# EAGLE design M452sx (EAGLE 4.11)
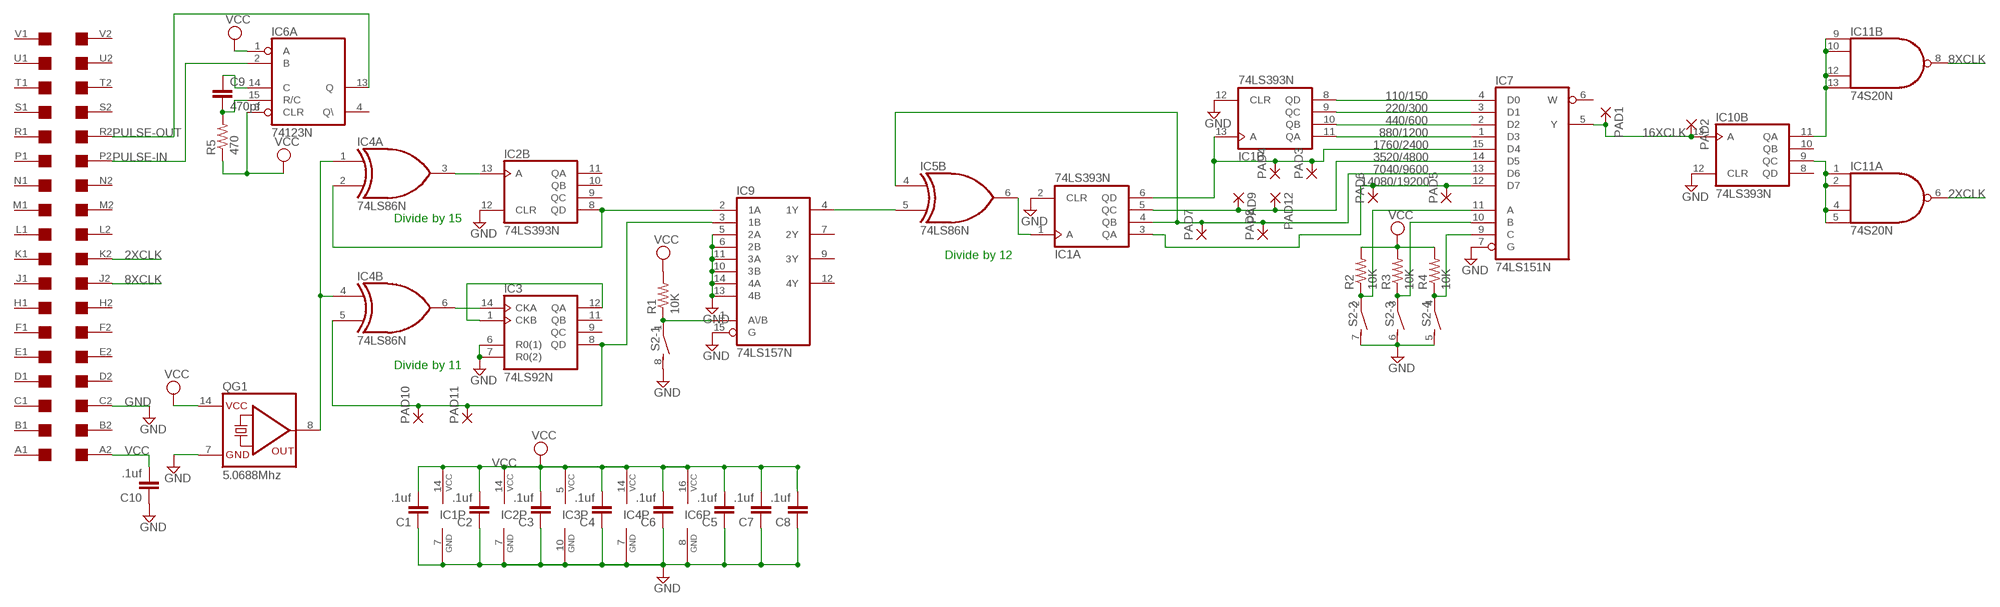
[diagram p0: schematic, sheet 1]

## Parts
C1  .1uf  C-EU050-025X075  [C050-025X075]
C2  .1uf  C-EU050-025X075  [C050-025X075]
C3  .1uf  C-EU050-025X075  [C050-025X075]
C4  .1uf  C-EU050-025X075  [C050-025X075]
C5  .1uf  C-EU050-025X075  [C050-025X075]
C6  .1uf  C-EU050-025X075  [C050-025X075]
C7  .1uf  C-EU050-025X075  [C050-025X075]
C8  .1uf  C-EU050-025X075  [C050-025X075]
C9  470pf  C-EU050-025X075  [C050-025X075]
C10  .1uf  C-EU050-025X075  [C050-025X075]
IC1  74LS393N  [DIL14]
IC2  74LS393N  [DIL14]
IC3  74LS92N  [DIL14]
IC4  74LS86N  [DIL14]
IC5  74LS86N  [DIL14]
IC6  74123N  [DIL16]
IC7  74LS151N  74151N  [DIL16]
IC9  74LS157N  [DIL16]
IC10  74LS393N  [DIL14]
IC11  74S20N  [DIL14]
PAD1  1,6/0,8  [1,6/0,8]
PAD2  1,6/0,8  [1,6/0,8]
PAD3  1,6/0,8  [1,6/0,8]
PAD4  1,6/0,8  [1,6/0,8]
PAD5  1,6/0,8  [1,6/0,8]
PAD6  1,6/0,8  [1,6/0,8]
PAD7  1,6/0,8  [1,6/0,8]
PAD8  1,6/0,8  [1,6/0,8]
PAD9  1,6/0,8  [1,6/0,8]
PAD10  1,6/0,8  [1,6/0,8]
PAD11  1,6/0,8  [1,6/0,8]
PAD12  1,6/0,8  [1,6/0,8]
QG1  5.0688Mhz  QG5860  [DIL14S]
R1  10K  R-US_0204/7  [0204/7]
R2  10K  R-US_0204/7  [0204/7]
R3  10K  R-US_0204/7  [0204/7]
R4  10K  R-US_0204/7  [0204/7]
R5  470  R-US_0204/7  [0204/7]
S2  DIP04S  [DIP04S]
U$1  DEC-FLIPCHIP  [DEC-FLIPCHIP]

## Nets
2XCLK: IC11.6(A:O) U$1.K2
8XCLK: IC11.8(B:O) U$1.J2
16XCLK: IC7.5(Y) IC10.13(B:A) PAD1.1(P) PAD2.1(P)
110/150: IC1.8(B:QD) IC7.4(D0)
220/300: IC1.9(B:QC) IC7.3(D1)
440/600: IC1.10(B:QB) IC7.2(D2)
880/1200: IC1.11(B:QA) IC7.1(D3)
1760/2400: IC1.6(A:QD) IC1.13(B:A) IC7.15(D4) PAD3.1(P) PAD4.1(P)
3520/4800: IC1.5(A:QC) IC7.14(D5) PAD9.1(P) PAD12.1(P)
7040/9600: IC1.4(A:QB) IC5.4(B:I0) IC7.13(D6) PAD7.1(P) PAD8.1(P)
14080/19200: IC1.3(A:QA) IC7.12(D7) PAD5.1(P) PAD6.1(P)
GND: C1.1 C2.1 C3.1 C4.1 C5.1 C6.1 C7.1 C8.1 C10.1 IC1.2(A:CLR) IC1.7(P:GND) IC1.12(B:CLR) IC2.7(P:GND) IC2.12(B:CLR) IC3.6(R0(1)) IC3.7(R0(2)) IC3.10(GND) IC4.7(P:GND) IC6.8(P:GND) IC7.7(G) IC9.5(2A) IC9.6(2B) IC9.10(3B) IC9.11(3A) IC9.13(4B) IC9.14(4A) IC9.15(G) IC10.12(B:CLR) QG1.7(GND) S2.5 S2.6 S2.7 S2.8 U$1.C2
N$1: IC4.1(A:I0) IC4.4(B:I0) QG1.8(OUT)
N$2: IC2.8(B:QD) IC4.2(A:I1) IC9.2(1A)
N$3: IC3.8(QD) IC4.5(B:I1) IC9.3(1B) PAD10.1(P) PAD11.1(P)
N$4: IC3.1(CKB) IC3.12(QA)
N$5: IC3.14(CKA) IC4.6(B:O)
N$6: IC2.13(B:A) IC4.3(A:O)
N$8: IC7.11(A) R2.1 S2.2
N$9: IC5.5(B:I1) IC9.4(1Y)
N$10: IC10.9(B:QC) IC11.1(A:I0) IC11.2(A:I1) IC11.4(A:I2) IC11.5(A:I3)
N$11: IC1.1(A:A) IC5.6(B:O)
N$12: IC10.11(B:QA) IC11.9(B:I0) IC11.10(B:I1) IC11.12(B:I2) IC11.13(B:I3)
N$13: IC7.10(B) R3.1 S2.3
N$14: IC7.9(C) R4.1 S2.4
N$17: IC9.1(A\/B) R1.1 S2.1
N$21: C9.2 IC6.15(A:R/C) R5.2
N$22: C9.1 IC6.14(A:C)
PULSE-IN: IC6.2(A:B) U$1.P2
PULSE-OUT: IC6.13(A:Q) U$1.R2
VCC: C1.2 C2.2 C3.2 C4.2 C5.2 C6.2 C7.2 C8.2 C10.2 IC1.14(P:VCC) IC2.14(P:VCC) IC3.5(VCC) IC4.14(P:VCC) IC6.1(A:A) IC6.3(A:CLR) IC6.16(P:VCC) QG1.14(VCC) R1.2 R2.2 R3.2 R4.2 R5.1 U$1.A2
Unconnected: IC2.1(A:A) IC2.2(A:CLR) IC2.3(A:QA) IC2.4(A:QB) IC2.5(A:QC) IC2.6(A:QD) IC2.9(B:QC) IC2.10(B:QB) IC2.11(B:QA) IC3.9(QC) IC3.11(QB) IC4.8(C:O) IC4.9(C:I0) IC4.10(C:I1) IC4.11(D:O) IC4.12(D:I0) IC4.13(D:I1) IC5.1(A:I0) IC5.2(A:I1) IC5.3(A:O) IC5.8(C:O) IC5.9(C:I0) IC5.10(C:I1) IC5.11(D:O) IC5.12(D:I0) IC5.13(D:I1) IC6.4(A:Q\) IC6.5(B:Q) IC6.6(B:C) IC6.7(B:R/C) IC6.9(B:A) IC6.10(B:B) IC6.11(B:CLR) IC6.12(B:Q\) IC7.6(W) IC9.7(2Y) IC9.9(3Y) IC9.12(4Y) IC10.1(A:A) IC10.2(A:CLR) IC10.3(A:QA) IC10.4(A:QB) IC10.5(A:QC) IC10.6(A:QD) IC10.8(B:QD) IC10.10(B:QB) U$1.A1 U$1.B1 U$1.B2 U$1.C1 U$1.D1 U$1.D2 U$1.E1 U$1.E2 U$1.F1 U$1.F2 U$1.H1 U$1.H2 U$1.J1 U$1.K1 U$1.L1 U$1.L2 U$1.M1 U$1.M2 U$1.N1 U$1.N2 U$1.P1 U$1.R1 U$1.S1 U$1.S2 U$1.T1 U$1.T2 U$1.U1 U$1.U2 U$1.V1 U$1.V2

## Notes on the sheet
- Divide by 15
- Divide by 12
- Divide by 11

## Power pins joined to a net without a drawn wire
GND: IC5.7(P:GND) IC7.8(GND) IC9.8(GND) IC10.7(P:GND) IC11.7(P:GND)
VCC: IC5.14(P:VCC) IC7.16(VCC) IC9.16(VCC) IC10.14(P:VCC) IC11.14(P:VCC)

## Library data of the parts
C1-C10 = rcl:C-EU: CAPACITOR, European symbol
IC1 IC2 IC10 = 74xx-us:74*393: Dual 4-bit decade and binary COUNTER
IC3 = 74xx-us:74*92: Decade, divide by twelve and binary COUNTER
IC4 IC5 = 74xx-us:74*86: Quad 2-input EXCLUSIV-OR (XOR) gate
IC6 = 74xx-us:74*123: Retriggerable monostable MULTIVIBRATOR
IC7 = 74xx-us:74*151: Data SELECTOR/MULTIPLEXER
IC9 = 74xx-us:74*157: Quadruple 2-line to 1-line data SELECTOR/MULTIPLEXER
IC11 = 74xx-us:74*20: Dual 4-input NAND gate
PAD1-PAD12 = wirepad:1,6/0,8: THROUGH-HOLE PAD
QG1 = crystal:QG5860: CRYSTAL RESONATOR
R1-R5 = rcl:R-US_: RESISTOR, American symbol
S2 = switch-dil:DIP04S: DIL/CODE SWITCH
U$1 = con-dec:DEC-FLIPCHIP: DEC Flip-Chip single card fingers

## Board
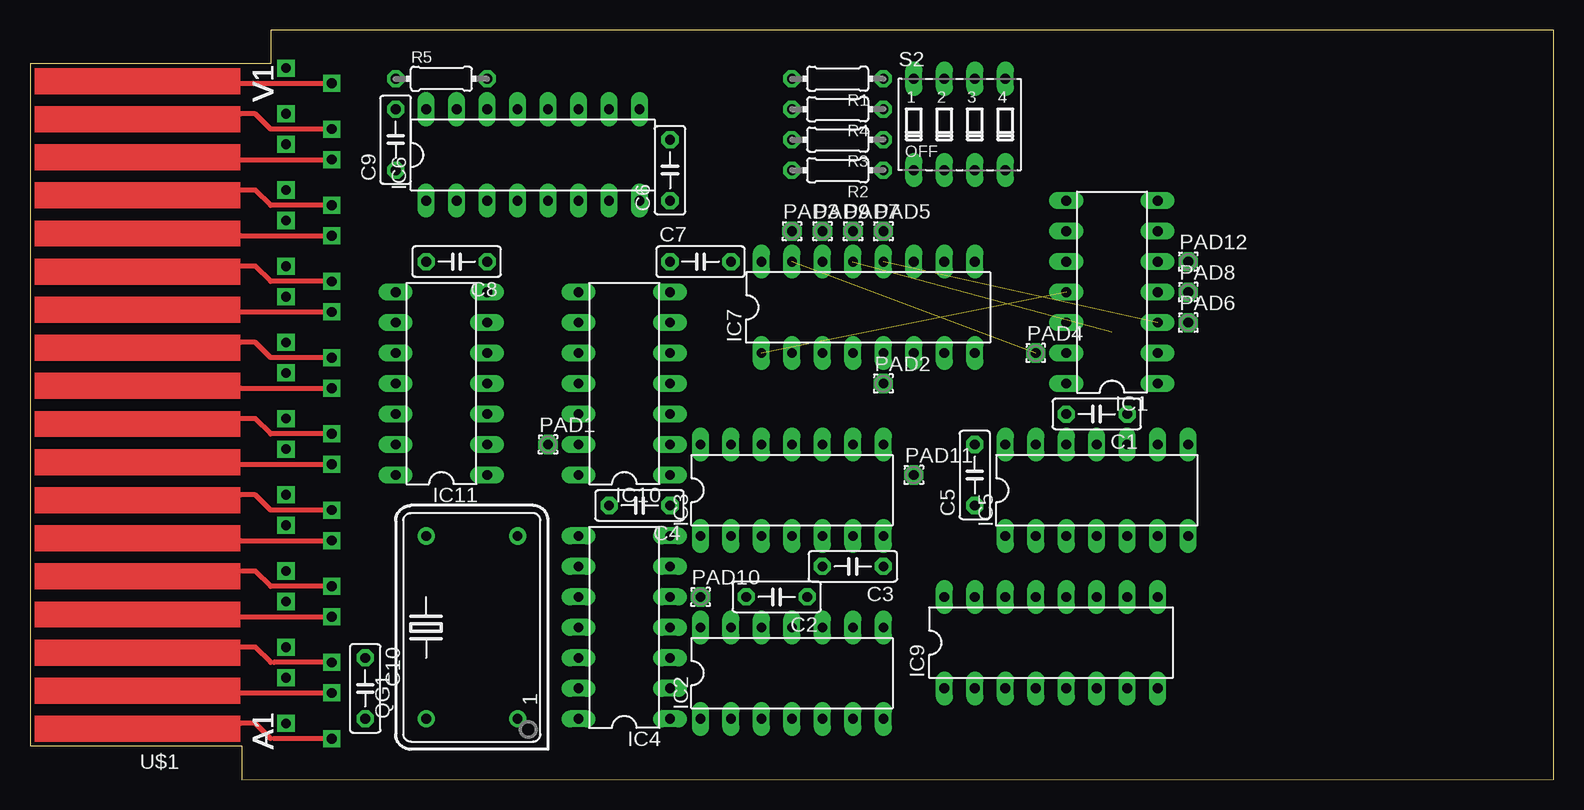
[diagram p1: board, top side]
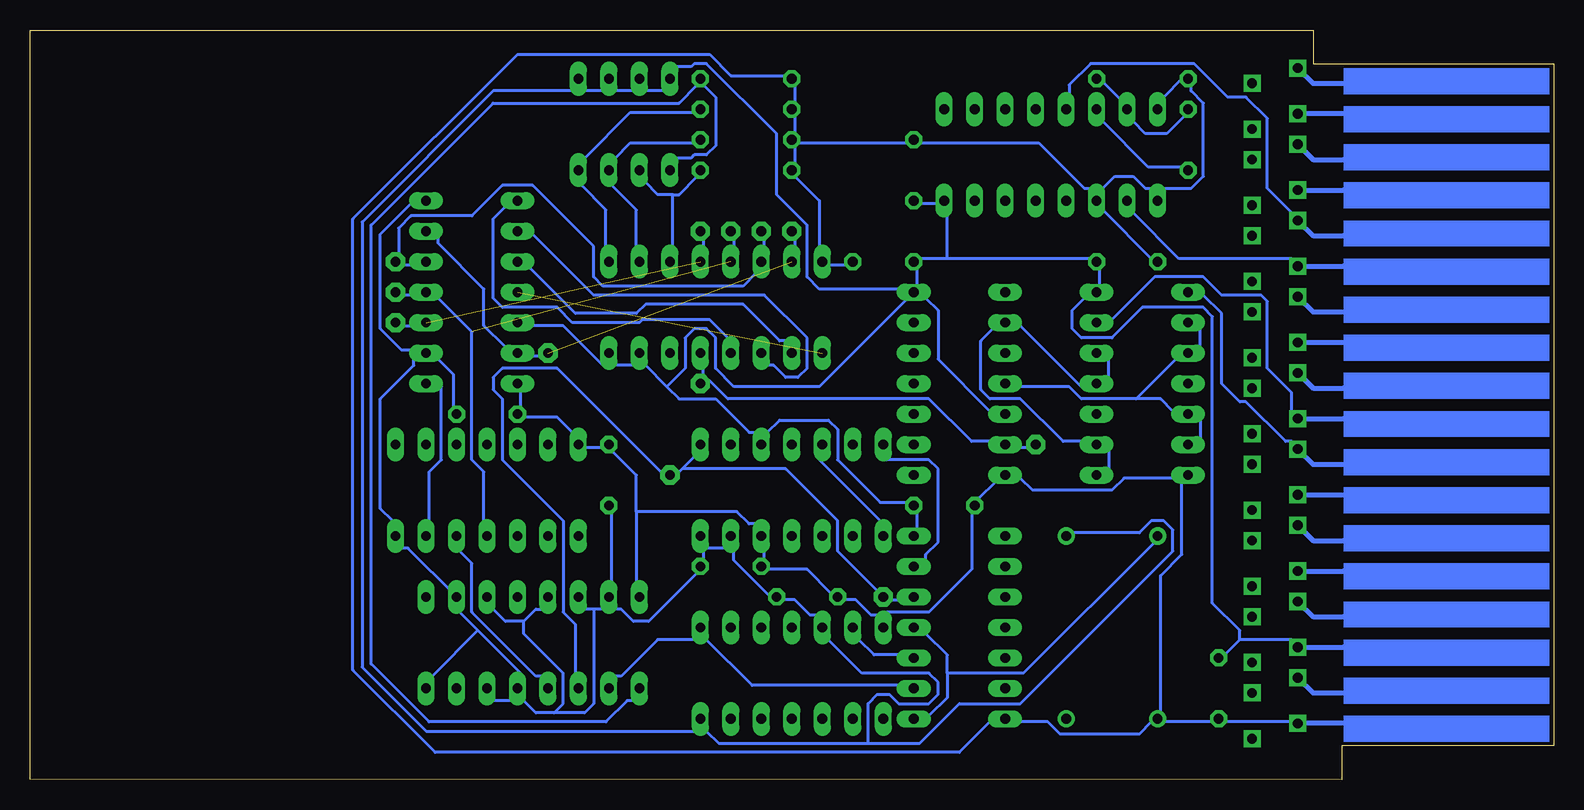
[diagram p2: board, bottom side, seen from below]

Size 126.98 x 62.48 mm. Coordinates in mm from the lower left corner, seen from the top.
Outline: 0,2.83 17.65,2.83 17.65,0 126.98,0.04 126.98,62.45 20.06,62.48 20.06,59.65 0,59.65 0,2.83
Copper layers (1*16): Top 0.035mm / dielectric 1.5mm / Bottom 0.035mm
Design rules "10mils": minimum track width 10mil, minimum drill 28mil, track to track 15mil, track to pad 10mil, pad to pad 10mil, via to via 10mil, smd to smd 10mil, copper to edge 40mil, drill to drill 10mil, minimum pad ring 12mil, minimum via ring 8mil, stop-mask expansion 0mil, vias tented up to drill 0mil, thermal gap 10mil

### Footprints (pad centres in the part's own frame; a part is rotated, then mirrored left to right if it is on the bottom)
C050-025X075 = drill 0.813 octagon: 1 -2.54,0; 2 2.54,0
DIL14 = drill 0.813 long: 1 -7.62,-3.81; 2 -5.08,-3.81; 3 -2.54,-3.81; 4 0,-3.81; 5 2.54,-3.81; 6 5.08,-3.81; 7 7.62,-3.81; 8 7.62,3.81; 9 5.08,3.81; 10 2.54,3.81; 11 0,3.81; 12 -2.54,3.81; 13 -5.08,3.81; 14 -7.62,3.81
DIL16 = drill 0.813 long: 1 -8.89,-3.81; 2 -6.35,-3.81; 3 -3.81,-3.81; 4 -1.27,-3.81; 5 1.27,-3.81; 6 3.81,-3.81; 7 6.35,-3.81; 8 8.89,-3.81; 9 8.89,3.81; 10 6.35,3.81; 11 3.81,3.81; 12 1.27,3.81; 13 -1.27,3.81; 14 -3.81,3.81; 15 -6.35,3.81; 16 -8.89,3.81
1,6/0,8 = drill 0.813 pad 1.6 octagon: 1 0,0
DIL14S = drill 0.813 round: 1 -7.62,-3.81; 7 7.62,-3.81; 8 7.62,3.81; 14 -7.62,3.81
0204/7 = drill 0.813 octagon: 1 -3.81,0; 2 3.81,0
DIP04S = drill 0.813 long: 1 -3.81,-3.81; 2 -1.27,-3.81; 3 1.27,-3.81; 4 3.81,-3.81; 5 3.81,3.81; 6 1.27,3.81; 7 -1.27,3.81; 8 -3.81,3.81
DEC-FLIPCHIP = drill 0.813 square: A1 -7.62,27.94; A2 -3.81,26.67; B1 -7.62,24.13; B2 -3.81,22.86; C1 -7.62,21.59; C2 -3.81,20.32; D1 -7.62,17.78; D2 -3.81,16.51; E1 -7.62,15.24; E2 -3.81,13.97; F1 -7.62,11.43; F2 -3.81,10.16; H1 -7.62,8.89; H2 -3.81,7.62; J1 -7.62,5.08; J2 -3.81,3.81; K1 -7.62,2.54; K2 -3.81,1.27; L1 -7.62,-1.27; L2 -3.81,-2.54; M1 -7.62,-3.81; M2 -3.81,-5.08; N1 -7.62,-7.62; N2 -3.81,-8.89; P1 -7.62,-10.16; P2 -3.81,-11.43; R1 -7.62,-13.97; R2 -3.81,-15.24; S1 -7.62,-16.51; S2 -3.81,-17.78; T1 -7.62,-20.32; T2 -3.81,-21.59; U1 -7.62,-22.86; U2 -3.81,-24.13; V1 -7.62,-26.67; V2 -3.81,-27.94

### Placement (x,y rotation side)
C1  88.9,30.48 180 top
C2  62.22,15.24 180 top
C3  68.58,17.78 180 top
C4  50.79,22.86 180 top
C5  78.73,25.4 90 top
C6  53.34,50.8 90 top
C7  55.88,43.18 0 top
C8  35.55,43.18 180 top
C9  30.48,53.34 90 top
C10  27.94,7.62 270 top
IC1  90.17,40.64 90 top
IC2  63.49,8.89 0 top
IC3  63.49,24.13 0 top
IC4  49.52,12.7 90 top
IC5  88.9,24.13 0 top
IC6  41.9,52.07 0 top
IC7  69.84,39.37 0 top
IC9  85.09,11.43 0 top
IC10  49.52,33.02 90 top
IC11  34.28,33.02 90 top
PAD1  43.17,27.94 0 top
PAD2  71.12,33.02 0 top
PAD3  63.49,45.72 0 top
PAD4  83.81,35.56 0 top
PAD5  71.12,45.72 0 top
PAD6  96.52,38.1 0 top
PAD7  68.58,45.72 0 top
PAD8  96.52,40.64 0 top
PAD9  66.04,45.72 0 top
PAD10  55.88,15.24 0 top
PAD11  73.66,25.4 0 top
PAD12  96.52,43.18 0 top
QG1  36.82,12.7 90 top
R1  67.31,58.42 180 top
R2  67.31,50.8 180 top
R3  67.31,53.34 180 top
R4  67.31,55.88 180 top
R5  34.28,58.42 0 top
S2  77.47,54.61 0 top
U$1  17.52,31.37 180 top

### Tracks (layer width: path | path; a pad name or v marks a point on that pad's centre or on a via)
2XCLK
  Bottom 0.254: U$1.K2 21.84,30.73 21.84,32.26 23.87,34.29 23.87,39.88 24.38,40.39 27.68,40.39 29.21,41.91 33.27,41.91 36.82,38.35 IC11.6
8XCLK
  Bottom 0.254: U$1.J2 21.84,28.19 22.35,28.19 25.65,31.5 26.16,31.5 27.68,33.02 27.68,38.86 29.21,40.39 IC11.8
16XCLK
  Bottom 0.254: PAD1.1 43.94,27.69 44.45,27.69 IC10.13 46.98,28.19 48.51,28.19 52.06,31.75 68.83,31.75 70.35,33.27 PAD2.1 70.86,33.78 70.86,34.29 IC7.5
110/150
  Bottom 0.254: IC7.4 68.83,36.83 70.35,38.35 75.94,38.35 76.2,38.1 81.78,38.1 83.05,39.37 87.62,39.37 88.39,40.13 88.39,46.74 87.37,47.75 IC1.8
220/300
  Bottom 0.254: IC7.3 65.53,34.54 65.02,34.54 64,33.53 62.99,33.53 62.22,34.29 62.22,36.83 65.78,40.39 80.01,40.39 85.09,45.47 IC1.9
440/600
  Bottom 0.254: IC7.2 64,36.58 64.51,36.58 67.56,39.62 75.69,39.62 76.45,38.86 81.53,38.86 85.34,42.67 IC1.10
880/1200  (1 unrouted)
1760/2400  (1 unrouted)
  Bottom 0.254: PAD4.1 84.58,35.31 85.09,35.31 IC1.13 87.37,36.07 89.15,37.85 89.15,40.89 92.96,44.7 92.96,45.21 IC1.6 | IC7.15 63.24,44.45 63.24,44.96 PAD3.1
3520/4800
  Bottom 0.254: IC1.5 95.25,42.93 95.75,42.93 PAD12.1 96.26,43.94 96.26,45.97 95.25,46.99 90.17,46.99 87.62,49.53 85.09,49.53 80.01,44.45 80.01,41.91 79.24,41.15 67.56,41.15 66.54,42.16 IC7.14 65.78,44.45 65.78,44.96 PAD9.1
7040/9600  (1 unrouted)
  Bottom 0.254: IC5.4 89.15,21.59 89.15,25.65 90.17,26.67 90.17,37.34 92.96,40.13 IC1.4 95.25,40.39 95.75,40.39 PAD8.1 | IC7.13 68.32,44.45 68.32,44.96 PAD7.1
14080/19200  (1 unrouted)
  Bottom 0.254: IC7.12 70.86,44.45 70.86,44.96 PAD5.1 | IC1.3 95.25,37.85 95.75,37.85 PAD6.1
GND
  Bottom 0.254: 57.14,3.05 69.59,3.05 70.61,4.06 IC2.7 71.62,4.06 93.98,4.06 99.31,9.4 99.31,46.48 88.39,57.4 81.78,57.4 S2.5 80.77,57.4 79.24,57.4 S2.6 78.23,57.4 76.7,57.4 S2.7 75.69,57.4 74.16,57.4 S2.8 73.15,59.44 71.88,59.44 71.62,59.69 70.61,59.69 64.77,53.85 64.77,48.77 62.22,46.23 62.22,41.91 61.21,40.89 54.6,40.89 IC10.7 | 57.14,3.05 52.83,3.05 49.52,6.35 44.45,6.35 31.75,19.05 31.75,20.83 32.51,21.59 33.52,21.59 34.54,20.57 40.13,20.57 QG1.7 | 80.01,14.22 80.77,14.22 IC9.14 | 80.01,14.22 79.24,14.22 IC9.15 | C5.1 78.48,22.35 78.48,16.51 IC9.15 | IC9.15 78.23,14.22 77.72,14.22 76.7,13.21 75.43,13.21 71.37,17.27 C3.1 70.86,18.29 70.86,19.05 IC3.7 70.61,19.3 69.08,19.3 IC3.6 68.32,19.05 68.32,18.29 65.27,15.24 C2.1 64.26,14.99 63.24,14.99 61.97,13.72 61.46,13.72 IC2.12 60.45,11.68 57.65,8.89 52.06,8.89 51.3,8.13 51.3,7.11 52.06,6.35 54.6,6.35 55.37,7.11 56.38,7.11 57.14,6.35 57.14,3.05 | C1.1 91.69,30.99 91.69,33.78 92.96,35.05 IC1.2 | IC1.7 95.25,48.01 97.79,45.47 97.79,37.59 96.01,35.81 95.25,35.81 IC1.2 | 85.85,13.21 84.83,14.22 84.32,14.22 IC9.13 | 85.85,13.21 87.37,13.21 88.39,14.22 IC9.11 | IC9.5 86.86,6.6 88.39,6.6 IC9.6 | 89.66,12.45 86.1,8.89 IC9.5 | 89.66,12.45 91.18,13.97 IC9.10 95.5,19.3 96.01,19.3 IC5.7 96.77,21.59 97.79,22.61 97.79,31.75 94.99,34.54 94.99,35.05 IC1.2 | 89.66,12.45 93.47,8.64 IC9.8 | 85.85,13.21 85.85,12.19 82.55,8.89 82.55,6.35 83.31,5.59 | 83.31,5.59 84.83,5.59 85.85,6.6 IC9.5 | 80.01,14.22 80.01,6.35 80.77,5.59 83.31,5.59 | IC4.7 53.08,20.83 53.08,22.35 C4.1 53.84,23.11 56.13,23.11 59.68,26.67 59.68,29.21 60.45,29.97 64.51,29.97 65.53,28.96 IC3.10 66.54,28.96 67.05,28.96 69.84,31.75 72.89,31.75 73.91,32.77
  Bottom 0.254: 73.91,32.77 75.69,34.54 IC7.7 76.7,34.54 78.23,34.54 IC7.8 79.24,34.54 82.55,37.85 85.09,37.85 IC1.12 | 26.16,11.68 21.84,11.68 U$1.C2 | 26.16,11.68 27.43,10.41 C10.1 | C6.1 52.83,48.01 51.3,48.01 IC6.8 50.54,46.99 50.54,43.43 | IC10.12 46.98,30.73 51.3,35.05 51.3,39.12 52.32,40.13 IC10.7 | IC10.7 53.08,41.15 53.08,42.67 C7.1 52.83,43.43 50.54,43.43 | 50.54,43.43 38.6,43.43 C8.1 37.84,42.67 37.84,41.15 IC11.7 39.11,40.13 40.13,39.12 40.13,37.59 39.36,36.83 36.82,36.83 34.28,39.37 29.21,39.37 28.44,38.61 28.44,14.73 26.16,12.45 26.16,11.68 | 73.91,32.77 72.39,34.29 72.39,36.83 71.62,37.59 70.61,37.59 69.84,36.83 69.84,34.29 68.32,32.77 61.21,32.77 IC10.7
N$1
  Bottom 0.254: 50.54,8.89 50.54,10.41 52.32,12.19 IC4.4 | 50.54,8.89 50.54,6.86 52.06,5.33 IC4.1 | 50.54,8.89 44.19,8.89 33.27,19.81 QG1.8
N$2
  Bottom 0.254: IC4.2 54.6,7.87 66.8,7.87 70.61,11.68 IC2.8 71.62,11.68 74.67,11.68 77.72,8.64 78.23,8.64 IC9.2
N$3
  Bottom 0.254: IC4.5 54.6,14.99 55.11,14.99 PAD10.1 59.68,19.05 59.68,21.59 64,25.91 72.64,25.91 | 72.64,25.91 72.89,25.65 PAD11.1 74.42,25.65 83.05,34.29 87.62,34.29 88.39,33.53 88.39,32.51 87.62,31.75 87.62,26.67 82.55,21.59 82.55,13.97 81.53,12.95 81.53,8.89 IC9.3 | 72.64,25.91 71.62,26.92 IC3.8
N$4
  Bottom 0.254: IC3.1 56.13,21.59 61.21,26.67 IC3.12
N$5
  Bottom 0.254: IC4.6 52.32,18.29 52.32,18.8 51.3,19.81 51.3,25.91 52.06,26.67 55.62,26.67 IC3.14
N$6
  Bottom 0.254: IC4.3 54.6,10.41 56.64,10.41 57.91,11.68 IC2.13
N$8
  Bottom 0.254: 73.4,48.77 74.67,48.77 75.69,49.78 S2.2 | 73.4,48.77 72.89,48.77 71.37,50.29 R2.1 | 73.4,48.77 73.4,44.45 IC7.11
N$9
  Bottom 0.254: IC9.4 84.32,8.64 84.83,8.64 90.17,13.97 90.17,18.03 91.18,19.05 IC5.5
N$10
  Bottom 0.254: IC11.1 37.08,25.91 37.08,27.43 IC11.2 39.36,28.19 40.89,28.19 44.45,31.75 46.98,31.75 47.75,32.51 47.75,36.58 46.73,37.59 IC10.9 44.45,37.85 39.36,32.77 IC11.4 37.08,33.53 37.08,35.05 IC11.5
N$11
  Bottom 0.254: IC5.6 93.72,21.59 93.72,25.65 92.7,26.67 92.7,32.77 IC1.1
N$12
  Bottom 0.254: IC11.9 29.46,37.59 29.46,36.07 IC11.10 31.49,35.05 34.79,31.75 | IC11.13 29.46,28.45 29.46,29.97 IC11.12 31.75,30.73 32.76,31.75 34.79,31.75 | 34.79,31.75 39.36,31.75 40.38,32.77 44.45,32.77 IC10.11
N$13
  Bottom 0.254: IC7.10 76.45,44.45 76.45,47.5 78.48,49.53 S2.3 78.23,51.82 76.96,53.09 71.62,53.09 R3.1
N$14
  Bottom 0.254: R4.1 71.62,55.63 76.96,55.63 80.77,51.82 S2.4 81.02,49.53 78.99,47.5 78.99,44.45 IC7.9
N$17
  Bottom 0.254: S2.1 73.15,51.82 71.88,51.82 71.62,52.07 70.61,52.07 69.84,52.83 69.84,56.9 70.86,57.91 R1.1 71.37,57.91 72.89,56.39 88.39,56.39 98.55,46.23 98.55,9.65 93.72,4.83 78.99,4.83 77.21,6.6 76.7,6.6 IC9.1
N$21
  Bottom 0.254: C9.2 30.73,55.37 32.25,53.85 34.03,53.85 35.05,54.86 IC6.15 36.06,56.64 37.59,58.17 R5.2
N$22
  Bottom 0.254: C9.1 30.98,51.05 33.78,51.05 37.59,54.86 IC6.14
PULSE-IN
  Bottom 0.254: U$1.P2 21.84,43.43 31.24,43.43 35.05,47.24 IC6.2
PULSE-OUT
  Bottom 0.254: U$1.R2 21.84,47.24 23.87,49.28 23.87,55.12 25.65,56.9 27.17,56.9 29.97,59.69 38.6,59.69 40.38,57.91 40.38,57.15 IC6.13
VCC
  Bottom 0.254: IC6.16 32.51,56.9 30.98,58.42 R5.1 30.22,57.91 30.22,57.4 29.21,56.39 29.21,50.29 30.22,49.28 32.51,49.28 IC6.1 33.52,49.28 34.03,49.28 35.05,50.29 36.57,50.29 37.59,49.28 IC6.3 | C8.2 33.52,43.43 37.59,47.5 IC6.3 | C7.2 58.92,42.93 60.45,42.93 IC7.16 61.21,44.45 61.21,48.26 63.24,50.29 R2.2 63.24,51.31 63.24,52.83 R3.2 | R3.2 62.99,53.09 53.84,53.09 C6.2 52.83,53.09 42.92,53.09 39.11,49.28 38.6,49.28 IC6.3 | R3.2 63.24,53.85 63.24,55.37 R4.2 63.24,56.39 63.24,57.91 R1.2 64,58.67 68.58,58.67 70.35,60.45 86.36,60.45 100.07,46.74 100.07,9.14 93.21,2.29 49.52,2.29 46.98,4.83 IC4.14 44.45,4.83 42.16,4.83 41.14,3.81 34.54,3.81 33.52,4.83 QG1.14 | U$1.A2 21.84,4.83 27.43,4.83 C10.2 28.44,4.83 32.51,4.83 QG1.14 | IC1.14 86.1,32.51 86.1,30.99 C1.2 85.85,30.23 83.05,30.23 81.78,28.96 IC5.14 80.77,27.69 79.24,27.69 C5.2 78.48,27.43 76.45,25.4 76.45,22.35 | 76.45,22.35 76.45,16.51 IC9.16 | 76.45,22.35 68.07,22.35 67.05,21.34 66.54,21.34 IC3.5 65.78,19.05 65.78,18.29 C3.2 65.53,17.53 62.22,17.53 60.19,15.49 C2.2 59.18,14.99 58.16,14.99 56.89,13.72 56.38,13.72 IC2.14 55.62,13.97 52.06,13.97 48.51,17.53 48.51,22.35 C4.2 48,23.37 46.48,24.89 IC10.14 44.45,25.15 43.43,24.13 36.82,24.13 35.81,25.15 31.75,25.15 IC11.14 30.98,24.89 30.98,18.8 32.76,17.02 32.76,5.59 QG1.14

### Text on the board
tNames: V1 | V1 | V1 | V1 | V1 | V1 | V1 | V1 | V1 | V1 | V1 | V1 | V1 | V1 | V1 | V1 | V1 | V1 | V1 | V1 | V1 | V1 | V1 | V1 | V1 | V1 | V1 | V1 | V1 | V1 | V1 | V1 | A1 | A1 | A1 | A1 | A1 | A1 | A1 | A1 | A1 | A1 | A1 | A1 | A1 | A1 | A1 | A1 | A1 | A1 | A1 | A1 | A1 | A1 | A1 | A1 | A1 | A1 | A1 | A1 | A1 | A1 | A1 | A1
